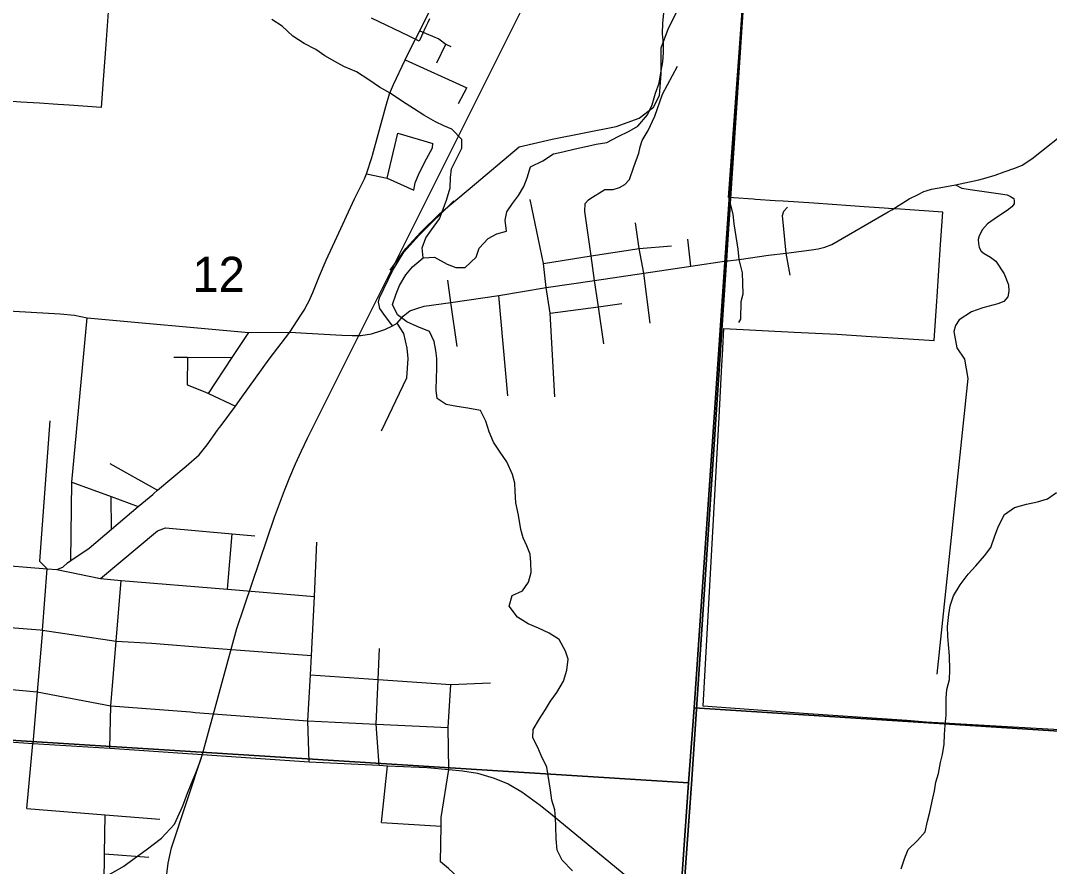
# Model space of a CAD drawing. Extents: x 39.8 to 73.8, y 13 to 35.
# Drawn here: x 42.701 to 43.927, y 32.071 to 33.079 of the extents above; entities that cross this region are included whole.
import ezdxf

# ---------------------------------------------------------------- set-up
doc = ezdxf.new("R2010")
doc.units = 0
for name, color, linetype in [('GM_X_City_Street', 7, 'Continuous'), ('GM_X_Corporation', 7, 'Continuous'), ('GM_X_County_Road', 7, 'Continuous'), ('GM_X_Minor_River', 7, 'Continuous'), ('GM_X_Rail_Line', 7, 'Continuous'), ('GM_X_Section_Text', 7, 'Continuous'), ('GM_X_State_Route', 7, 'Continuous'), ('GM_X_Township_Road', 7, 'Continuous')]:
    doc.layers.add(name, color=color, linetype=linetype)

msp = doc.modelspace()

# ---------------------------------------------------------------- linework, layer by layer
at = {"layer": 'GM_X_City_Street'}
for p, q in [((43.4996, 32.7863), (43.496, 32.8184)), ((43.2813, 32.6318), (43.2708, 32.7514)), ((42.7242, 32.4408), (42.7361, 32.6024)), ((42.8071, 32.5515), (42.8641, 32.5196)), ((42.8091, 32.473), (42.8088, 32.5119)), ((42.9472, 32.4016), (42.9529, 32.4676)), ((42.7082, 32.1403), (42.7153, 32.218)), ((43.1311, 32.1236), (43.1379, 32.1911)), ((43.1311, 32.1236), (43.202, 32.1196)), ((42.8008, 32.0865), (42.8535, 32.0825))]:
    msp.add_line(p, q, dxfattribs=at)
for points in [[(43.1439, 32.7153), (43.1335, 32.7292), (43.1288, 32.7359), (43.1281, 32.7398), (43.1272, 32.7436), (43.1286, 32.7489), (43.1442, 32.7807), (43.1576, 32.8033), (43.1758, 32.8232), (43.2173, 32.8641)], [(43.3375, 32.6306), (43.3321, 32.7306), (43.3271, 32.7609), (43.3241, 32.7896), (43.3082, 32.8658)], [(43.5573, 32.7942), (43.556, 32.8068), (43.5513, 32.8368), (43.55, 32.8485), (43.5467, 32.8605)], [(43.618, 32.7759), (43.6132, 32.8019), (43.6089, 32.8467), (43.6105, 32.852), (43.6148, 32.8569)], [(43.4511, 32.7187), (43.4435, 32.7782), (43.438, 32.8073), (43.4335, 32.838)], [(43.3241, 32.7896), (43.3809, 32.7987), (43.438, 32.8073), (43.4765, 32.8106)], [(43.5567, 32.7195), (43.559, 32.7234), (43.5597, 32.7442), (43.562, 32.7536), (43.561, 32.7783), (43.5573, 32.7942)], [(43.2212, 32.6909), (43.2135, 32.7433), (43.21, 32.7698)], [(43.3959, 32.694), (43.3894, 32.738), (43.3849, 32.7692)], [(43.3321, 32.7306), (43.3894, 32.738), (43.4175, 32.7421)], [(42.616, 32.7381), (42.6207, 32.7378), (42.6326, 32.7364), (42.6437, 32.7356), (42.7479, 32.7297), (42.7652, 32.7282), (42.7801, 32.7247), (42.9726, 32.7075), (43.0218, 32.7079)], [(42.7605, 32.436), (42.7619, 32.5291), (42.7801, 32.7247)], [(43.1308, 32.5904), (43.1611, 32.6535), (43.1626, 32.6765), (43.1615, 32.6887), (43.1574, 32.7062), (43.1495, 32.7185)], [(42.9246, 32.6346), (42.9528, 32.6775), (42.9726, 32.7075)], [(42.8832, 32.6781), (42.8995, 32.6779), (42.9528, 32.6775)], [(42.8995, 32.6779), (42.8994, 32.645), (42.9203, 32.6366), (42.9246, 32.6346), (42.9567, 32.6198)], [(42.7619, 32.5291), (42.8088, 32.5119), (42.841, 32.5001)], [(42.796, 32.4143), (42.8641, 32.4713), (42.8733, 32.4746), (42.9529, 32.4676), (42.98, 32.4653)], [(43.0446, 32.1959), (43.043, 32.2449), (43.0463, 32.2996), (43.0475, 32.3226), (43.0512, 32.393), (43.0537, 32.4578)], [(42.7268, 32.3529), (42.7326, 32.4261), (42.7238, 32.4347), (42.7242, 32.4408)], [(42.7439, 32.4253), (42.796, 32.4143), (42.8207, 32.4122), (42.9472, 32.4016), (43.0512, 32.393)], [(42.8072, 32.2124), (42.8082, 32.2626), (42.8146, 32.3397), (42.8207, 32.4122)], [(42.7268, 32.3529), (42.8146, 32.3397), (42.857, 32.3372), (42.9259, 32.332), (43.0475, 32.3226)], [(43.1282, 32.1919), (43.1246, 32.2409), (43.1271, 32.2941), (43.1287, 32.3309)], [(43.0463, 32.2996), (43.1271, 32.2941), (43.2134, 32.2882), (43.2609, 32.2903)], [(42.5801, 32.291), (42.6514, 32.2858), (42.7207, 32.2794), (42.8082, 32.2626), (42.9031, 32.2555), (42.909, 32.255)], [(43.2154, 31.9021), (43.2151, 31.9245), (43.2277, 32.0524), (43.2164, 32.0638), (43.2106, 32.0689), (43.2012, 32.0771), (43.202, 32.1196), (43.2022, 32.1299), (43.2112, 32.1871), (43.2102, 32.2368), (43.2134, 32.2882)], [(42.909, 32.255), (43.043, 32.2449), (43.1246, 32.2409), (43.2102, 32.2368)], [(42.7082, 32.1403), (42.8017, 32.1328), (42.8669, 32.1276)], [(42.8002, 32.0512), (42.8008, 32.0865), (42.8017, 32.1328)]]:
    msp.add_lwpolyline(points, dxfattribs=at)
at = {"layer": 'GM_X_Corporation'}
for points in [[(43.3481, 29.9766), (43.3525, 30.036), (43.3561, 30.0855), (43.3611, 30.1536), (43.3611, 30.1764), (43.4119, 30.9413), (43.4278, 31.1804), (43.4594, 31.6102), (43.4604, 31.6234), (43.4879, 31.9992), (43.5004, 32.1696), (43.5417, 32.788), (43.542, 32.7932), (43.5449, 32.8368), (43.546, 32.8532), (43.5465, 32.861), (43.5681, 33.1854), (43.5817, 33.4098), (43.6158, 33.865), (41.863, 33.865), (41.863, 28.2309)], [(48.663, 33.865), (43.6158, 33.865), (43.5817, 33.4098), (43.5681, 33.1854), (43.5465, 32.861), (43.546, 32.8532), (43.5449, 32.8368), (43.542, 32.7932), (43.5417, 32.788), (43.5004, 32.1696), (43.4879, 31.9992), (43.4604, 31.6234), (43.4594, 31.6102), (43.4278, 31.1804), (43.4119, 30.9413), (43.3611, 30.1764), (43.3611, 30.1536), (43.3561, 30.0855), (43.3525, 30.036), (43.3481, 29.9766)], [(44.0083, 32.23), (43.7802, 32.2434), (43.7569, 32.2451), (43.6396, 32.2534), (43.5141, 32.2623), (43.5332, 32.6065), (43.5366, 32.6685), (43.5373, 32.6808), (43.5391, 32.7123), (43.6227, 32.708), (43.6737, 32.7054), (43.7147, 32.7027), (43.7344, 32.7014), (43.7897, 32.6977), (43.7928, 32.7448), (43.7932, 32.7504), (43.7972, 32.8123), (43.7999, 32.8507), (43.7494, 32.8542), (43.7405, 32.8548), (43.73, 32.8555), (43.7062, 32.8572), (43.69, 32.8583), (43.6462, 32.8613), (43.6097, 32.8638), (43.6, 32.8644), (43.5768, 32.866), (43.5737, 32.8663), (43.5505, 32.8678), (43.5445, 32.8683), (43.557, 33.0409), (43.5667, 33.1746)], [(42.8053, 33.0892), (42.8024, 33.0506), (42.7993, 33.0084), (42.7968, 32.9753), (42.7585, 32.978), (42.745, 32.9789), (42.7231, 32.9804), (42.7012, 32.9819), (42.6807, 32.9834)], [(43.1882, 33.0812), (43.186, 33.0765), (43.1838, 33.0718), (43.1818, 33.0675), (43.1811, 33.0661), (43.1805, 33.0648), (43.1785, 33.0605), (43.1764, 33.0562), (43.1757, 33.0546), (43.171, 33.0568), (43.1639, 33.0603), (43.119, 33.082)]]:
    msp.add_lwpolyline(points, dxfattribs=at)
for points in [[(43.573, 33.2772), (44.5795, 33.2157), (44.516, 32.1957), (43.5036, 32.2603), (43.567, 33.1836)], [(43.567, 33.1836), (43.5036, 32.2603), (43.4969, 32.1712), (42.505, 32.2334), (42.5452, 32.7074), (42.566, 33.2401)], [(43.5036, 32.2603), (44.516, 32.1957), (44.4392, 31.1377), (43.4282, 31.1846), (43.4969, 32.1712)], [(42.505, 32.2334), (43.4969, 32.1712), (43.4282, 31.1846), (42.4262, 31.2112)]]:
    msp.add_lwpolyline(points, close=True, dxfattribs=at)
at = {"layer": 'GM_X_County_Road'}
for points in [[(43.7999, 32.8805), (43.8152, 32.8834), (43.8429, 32.8892), (43.8516, 32.8918), (43.8622, 32.895), (43.8732, 32.8987), (43.8858, 32.9031), (43.8946, 32.9069), (43.9062, 32.9141), (43.954, 32.9525)], [(43.7349, 32.8511), (43.7393, 32.8537), (43.76, 32.8666), (43.7696, 32.8715), (43.7771, 32.8752), (43.78, 32.876)], [(43.78, 32.876), (43.7866, 32.878), (43.7999, 32.8805)], [(43.6132, 32.8019), (43.6433, 32.8059), (43.6514, 32.8071), (43.6594, 32.8091), (43.6678, 32.8124), (43.7349, 32.8511)], [(43.5442, 32.7928), (43.5573, 32.7942), (43.592, 32.7996), (43.6132, 32.8019)], [(43.1302, 32.7094), (43.1349, 32.7108), (43.1439, 32.7153), (43.1495, 32.7185), (43.1567, 32.7269), (43.1648, 32.7331), (43.1741, 32.7366), (43.1817, 32.7386), (43.2135, 32.7433), (43.2708, 32.7514), (43.3271, 32.7609), (43.3849, 32.7692), (43.4435, 32.7782), (43.4996, 32.7863), (43.5422, 32.7926), (43.5442, 32.7928)], [(43.0218, 32.7079), (43.0416, 32.7068), (43.0836, 32.7041), (43.0961, 32.7039), (43.1061, 32.7039), (43.1189, 32.706), (43.1302, 32.7094)], [(42.5152, 32.3719), (42.5863, 32.365), (42.6575, 32.3586), (42.7239, 32.3531)], [(42.7239, 32.3531), (42.7268, 32.3529), (42.7207, 32.2794), (42.7153, 32.218)], [(42.5756, 32.2229), (42.5849, 32.2254), (42.5918, 32.226), (42.6473, 32.2227), (42.7153, 32.218)], [(42.7153, 32.218), (42.8072, 32.2124), (43.0446, 32.1959)], [(43.0446, 32.1959), (43.1282, 32.1919), (43.1379, 32.1911), (43.1854, 32.1893), (43.2112, 32.1871)], [(43.2112, 32.1871), (43.2274, 32.1855), (43.2455, 32.1827), (43.2652, 32.1767), (43.2818, 32.1697), (43.2982, 32.1603), (43.3202, 32.1443), (43.3345, 32.133), (43.4449, 32.042), (43.4768, 32.0173), (43.489, 32.0089)]]:
    msp.add_lwpolyline(points, dxfattribs=at)
at = {"layer": 'GM_X_Minor_River'}
for p, q in [((43.9128, 32.5057), (43.9246, 32.5092)), ((43.9246, 32.5092), (43.9356, 32.5167)), ((43.8735, 32.4906), (43.8852, 32.4989)), ((43.8852, 32.4989), (43.8996, 32.5031)), ((43.8996, 32.5031), (43.9128, 32.5057)), ((43.8663, 32.4769), (43.8735, 32.4906)), ((43.8621, 32.4652), (43.8663, 32.4769)), ((43.8572, 32.4515), (43.8621, 32.4652)), ((43.8496, 32.4413), (43.8572, 32.4515)), ((43.8394, 32.4296), (43.8496, 32.4413)), ((43.8303, 32.4197), (43.8394, 32.4296)), ((43.8204, 32.4068), (43.8303, 32.4197)), ((43.8125, 32.3939), (43.8204, 32.4068)), ((43.8087, 32.3818), (43.8125, 32.3939)), ((43.8072, 32.3716), (43.8087, 32.3818)), ((43.8053, 32.3572), (43.8072, 32.3716)), ((43.806, 32.3454), (43.8053, 32.3572)), ((43.8068, 32.3359), (43.806, 32.3454)), ((43.8079, 32.3223), (43.8068, 32.3359)), ((43.8083, 32.3052), (43.8079, 32.3223)), ((43.8079, 32.2943), (43.8083, 32.3052)), ((43.8045, 32.2821), (43.8079, 32.2943)), ((43.8038, 32.2719), (43.8045, 32.2821)), ((43.8038, 32.2617), (43.8038, 32.2719)), ((43.8026, 32.2397), (43.8041, 32.2518)), ((43.8041, 32.2518), (43.8038, 32.2617)), ((43.8019, 32.2287), (43.8026, 32.2397)), ((43.8015, 32.2169), (43.8019, 32.2287)), ((43.7996, 32.2048), (43.8015, 32.2169)), ((43.7973, 32.1953), (43.7996, 32.2048)), ((43.7946, 32.1821), (43.7973, 32.1953)), ((43.7916, 32.1718), (43.7946, 32.1821)), ((43.7901, 32.1616), (43.7916, 32.1718)), ((43.7871, 32.1491), (43.7901, 32.1616)), ((43.7844, 32.1362), (43.7871, 32.1491)), ((43.7818, 32.1252), (43.7844, 32.1362)), ((43.7787, 32.1127), (43.7818, 32.1252)), ((43.7696, 32.1025), (43.7787, 32.1127)), ((43.7545, 32.0816), (43.7587, 32.0915)), ((43.7587, 32.0915), (43.7696, 32.1025)), ((43.7503, 32.0687), (43.7545, 32.0816))]:
    msp.add_line(p, q, dxfattribs=at)
for points in [[(43.197, 32.6766), (43.1958, 32.686), (43.1936, 32.6966), (43.1883, 32.7088), (43.1735, 32.7145), (43.161, 32.7201), (43.1501, 32.7285), (43.144, 32.7406), (43.1482, 32.7535), (43.1523, 32.7633), (43.1599, 32.7762), (43.1679, 32.7857), (43.1807, 32.7963), (43.194, 32.7971), (43.2091, 32.7887), (43.2193, 32.785), (43.2307, 32.785), (43.2436, 32.7971), (43.2474, 32.8077), (43.258, 32.8195), (43.2682, 32.8248), (43.2799, 32.8282), (43.2784, 32.8414), (43.2803, 32.8513), (43.2871, 32.8611), (43.2943, 32.8706), (43.3004, 32.8812), (43.3046, 32.8918), (43.3083, 32.9047), (43.3231, 32.9119), (43.336, 32.9203), (43.347, 32.9226), (43.3617, 32.926), (43.3765, 32.9294), (43.3867, 32.9317), (43.3996, 32.9339), (43.4128, 32.9408), (43.4261, 32.9472), (43.4363, 32.9533), (43.4481, 32.9665), (43.4534, 32.9787), (43.4575, 32.9923), (43.4617, 33.0044), (43.4643, 33.0192), (43.4662, 33.0298), (43.467, 33.0404), (43.467, 33.0511), (43.4659, 33.0632), (43.4663, 33.0764), (43.4674, 33.0878)], [(43.1807, 32.7963), (43.1792, 32.8081), (43.1838, 32.8202), (43.1906, 32.8297), (43.2001, 32.8429), (43.2035, 32.8524), (43.2084, 32.8649), (43.2126, 32.8797), (43.2133, 32.8922), (43.2145, 32.9024), (43.2201, 32.9142), (43.2266, 32.9271), (43.2266, 32.9373), (43.2148, 32.9498), (43.205, 32.9536), (43.1952, 32.9585), (43.1815, 32.9661), (43.169, 32.9741), (43.1558, 32.9824), (43.1414, 32.9926), (43.1285, 32.9995), (43.1157, 33.0082), (43.1013, 33.018), (43.0861, 33.0241), (43.0752, 33.0301), (43.0634, 33.037), (43.0528, 33.0445), (43.0388, 33.0517), (43.0252, 33.0605), (43.0127, 33.0722), (43.0002, 33.0802)], [(43.3585, 32.0664), (43.3464, 32.0789), (43.3403, 32.091), (43.3392, 32.1043), (43.3388, 32.1195), (43.3381, 32.1293), (43.3373, 32.1388), (43.3339, 32.1502), (43.3324, 32.1623), (43.3279, 32.1896), (43.3214, 32.2036), (43.3173, 32.2131), (43.3112, 32.2248), (43.3116, 32.2347), (43.3192, 32.2472), (43.3264, 32.2582), (43.3324, 32.2684), (43.34, 32.2786), (43.3479, 32.2923), (43.3517, 32.3052), (43.3533, 32.3184), (43.3502, 32.3279), (43.3427, 32.3419), (43.3309, 32.3495), (43.3181, 32.3552), (43.3056, 32.3605), (43.2931, 32.3685), (43.2832, 32.3813), (43.2866, 32.3942), (43.2988, 32.3999), (43.3063, 32.4101), (43.3094, 32.4215), (43.309, 32.4336), (43.3079, 32.4435), (43.3041, 32.4534), (43.2999, 32.4628), (43.2969, 32.4727), (43.2942, 32.4897), (43.2912, 32.5045), (43.2901, 32.5185), (43.2897, 32.528), (43.2871, 32.5382), (43.2802, 32.5534), (43.2723, 32.5648), (43.2643, 32.5769), (43.2591, 32.589), (43.2553, 32.6019), (43.2488, 32.6144), (43.2337, 32.6174), (43.2208, 32.6193), (43.2079, 32.6216), (43.1973, 32.6288), (43.1962, 32.6387), (43.1966, 32.6538), (43.197, 32.6633), (43.197, 32.6766)]]:
    msp.add_lwpolyline(points, dxfattribs=at)
at = {"layer": 'GM_X_Rail_Line'}
for points in [[(42.9175, 32.205), (42.9584, 32.355), (43.0035, 32.4874), (43.0092, 32.5034), (43.0152, 32.5194), (43.0216, 32.5352), (43.0284, 32.5508), (43.0355, 32.5663), (43.0429, 32.5817), (43.1926, 32.8811), (43.5132, 33.5223)], [(43.1411, 32.7817), (43.1598, 32.8074), (43.1779, 32.827), (43.1999, 32.8487), (43.2367, 32.8795), (43.2949, 32.9285), (43.3345, 32.9377), (43.4106, 32.9527), (43.4379, 32.9627), (43.4552, 32.9757), (43.4623, 32.9898), (43.4641, 33.0155), (43.4641, 33.0465), (43.4731, 33.0698), (43.4858, 33.0949)], [(42.7183, 32.0449), (42.7579, 32.047), (42.7762, 32.0508), (42.7964, 32.0567), (42.8108, 32.0643), (42.8238, 32.0719), (42.8361, 32.081), (42.8506, 32.0913), (42.8687, 32.1053), (42.8843, 32.1218), (42.8943, 32.1435), (42.8997, 32.1588), (42.9095, 32.1828), (42.9125, 32.19), (42.9152, 32.1975), (42.9175, 32.205)], [(42.9194, 31.9872), (42.9067, 31.997), (42.9017, 32.0008), (42.8962, 32.0054), (42.8855, 32.0202), (42.8808, 32.0296), (42.8781, 32.0399), (42.8758, 32.0496), (42.8746, 32.0592), (42.8765, 32.0755), (42.8807, 32.0936), (42.9175, 32.205)]]:
    msp.add_lwpolyline(points, dxfattribs=at)
at = {"layer": 'GM_X_State_Route'}
for points in [[(43.166, 33.0461), (43.1766, 33.0667), (43.1952, 33.1049), (43.2452, 33.2075), (43.2538, 33.2303), (43.2596, 33.252), (43.2622, 33.2671), (43.2655, 33.3849), (43.2673, 33.4176), (43.2688, 33.428), (43.2714, 33.438), (43.2776, 33.4547), (43.286, 33.4727), (43.3028, 33.5003), (43.3265, 33.5464), (43.3591, 33.6015), (43.3918, 33.6555), (43.432, 33.7178), (43.4711, 33.78)], [(43.1129, 32.8963), (43.1197, 32.9169), (43.1202, 32.9188), (43.1359, 32.9766), (43.1406, 32.9917), (43.1451, 33.0028), (43.159, 33.0323), (43.166, 33.0461)], [(43.0429, 32.7416), (43.0443, 32.7442), (43.0491, 32.7551), (43.0572, 32.7748), (43.0648, 32.7934), (43.0776, 32.8211), (43.0989, 32.8666), (43.1107, 32.8905), (43.1116, 32.8923), (43.1129, 32.8963)], [(43.0218, 32.7079), (43.0349, 32.7279), (43.0387, 32.7339), (43.0429, 32.7416)], [(42.9397, 32.5966), (42.9567, 32.6198), (42.9644, 32.6304), (42.997, 32.6757), (43.0218, 32.7079)], [(42.8641, 32.5196), (42.8982, 32.5482), (42.9135, 32.5617), (42.9231, 32.5738), (42.9356, 32.5909), (42.938, 32.5942), (42.9397, 32.5966)], [(42.7568, 32.4329), (42.7605, 32.436), (42.7826, 32.4504), (42.8091, 32.473), (42.8249, 32.4865), (42.841, 32.5001), (42.8582, 32.5146), (42.8597, 32.5158), (42.8641, 32.5196)], [(42.501, 32.2163), (42.5021, 32.2264), (42.5086, 32.2975), (42.5152, 32.3719), (42.5212, 32.444), (42.5922, 32.4379), (42.664, 32.4313), (42.7326, 32.4261), (42.7439, 32.4253), (42.7509, 32.4279), (42.7568, 32.4329)]]:
    msp.add_lwpolyline(points, dxfattribs=at)
at = {"layer": 'GM_X_Township_Road'}
for p, q in [((43.1968, 33.0288), (43.2076, 33.051)), ((43.159, 33.0323), (43.2325, 32.9987)), ((43.2225, 32.9803), (43.2325, 32.9987)), ((43.1376, 32.8913), (43.1504, 32.9449)), ((43.1504, 32.9449), (43.1922, 32.9325))]:
    msp.add_line(p, q, dxfattribs=at)
for points in [[(43.1766, 33.0667), (43.1994, 33.0572), (43.2076, 33.051), (43.2134, 33.0481)], [(43.3792, 32.8667), (43.3972, 32.8776), (43.4071, 32.8779), (43.4145, 32.8802), (43.421, 32.8839), (43.4265, 32.8898), (43.4315, 32.9048), (43.4378, 32.9209), (43.4391, 32.9287), (43.4417, 32.9362), (43.4488, 32.9481), (43.4566, 32.9651), (43.4658, 32.9913), (43.4836, 33.0246)], [(43.1694, 32.8769), (43.1711, 32.8855), (43.1756, 32.8971), (43.1846, 32.9143), (43.1915, 32.9272), (43.1922, 32.9325)], [(43.1129, 32.8963), (43.1376, 32.8913), (43.1694, 32.8769)], [(43.8152, 32.8834), (43.8224, 32.8794), (43.8325, 32.8776), (43.8688, 32.8726), (43.8767, 32.8712), (43.8807, 32.8696), (43.8846, 32.8669), (43.8851, 32.8638), (43.8848, 32.8608), (43.8821, 32.8571), (43.8765, 32.8527), (43.8663, 32.8458)], [(43.3849, 32.7692), (43.3809, 32.7987), (43.3733, 32.8514), (43.3735, 32.8611), (43.3775, 32.8656), (43.3792, 32.8667)], [(43.8663, 32.8458), (43.8611, 32.8423), (43.8572, 32.8396), (43.8532, 32.837), (43.8471, 32.8302), (43.8433, 32.8226), (43.8421, 32.8181), (43.8423, 32.8134), (43.8434, 32.8088), (43.8458, 32.8043), (43.8493, 32.8014), (43.8569, 32.7971), (43.8629, 32.7922), (43.8731, 32.7774), (43.8781, 32.7641), (43.8786, 32.7568), (43.8774, 32.7499), (43.8726, 32.7445), (43.8655, 32.7414), (43.8476, 32.7368), (43.834, 32.7319), (43.8195, 32.7224), (43.8149, 32.7157), (43.8131, 32.7088), (43.8168, 32.6891), (43.8257, 32.6756), (43.8296, 32.6527), (43.7926, 32.3004)]]:
    msp.add_lwpolyline(points, dxfattribs=at)

# ---------------------------------------------------------------- texts
at = {"layer": 'GM_X_Section_Text'}
msp.add_text('12', height=0.04186, rotation=0, dxfattribs=at).set_placement((42.9057, 32.7557))

doc.saveas('drawing.dxf')
